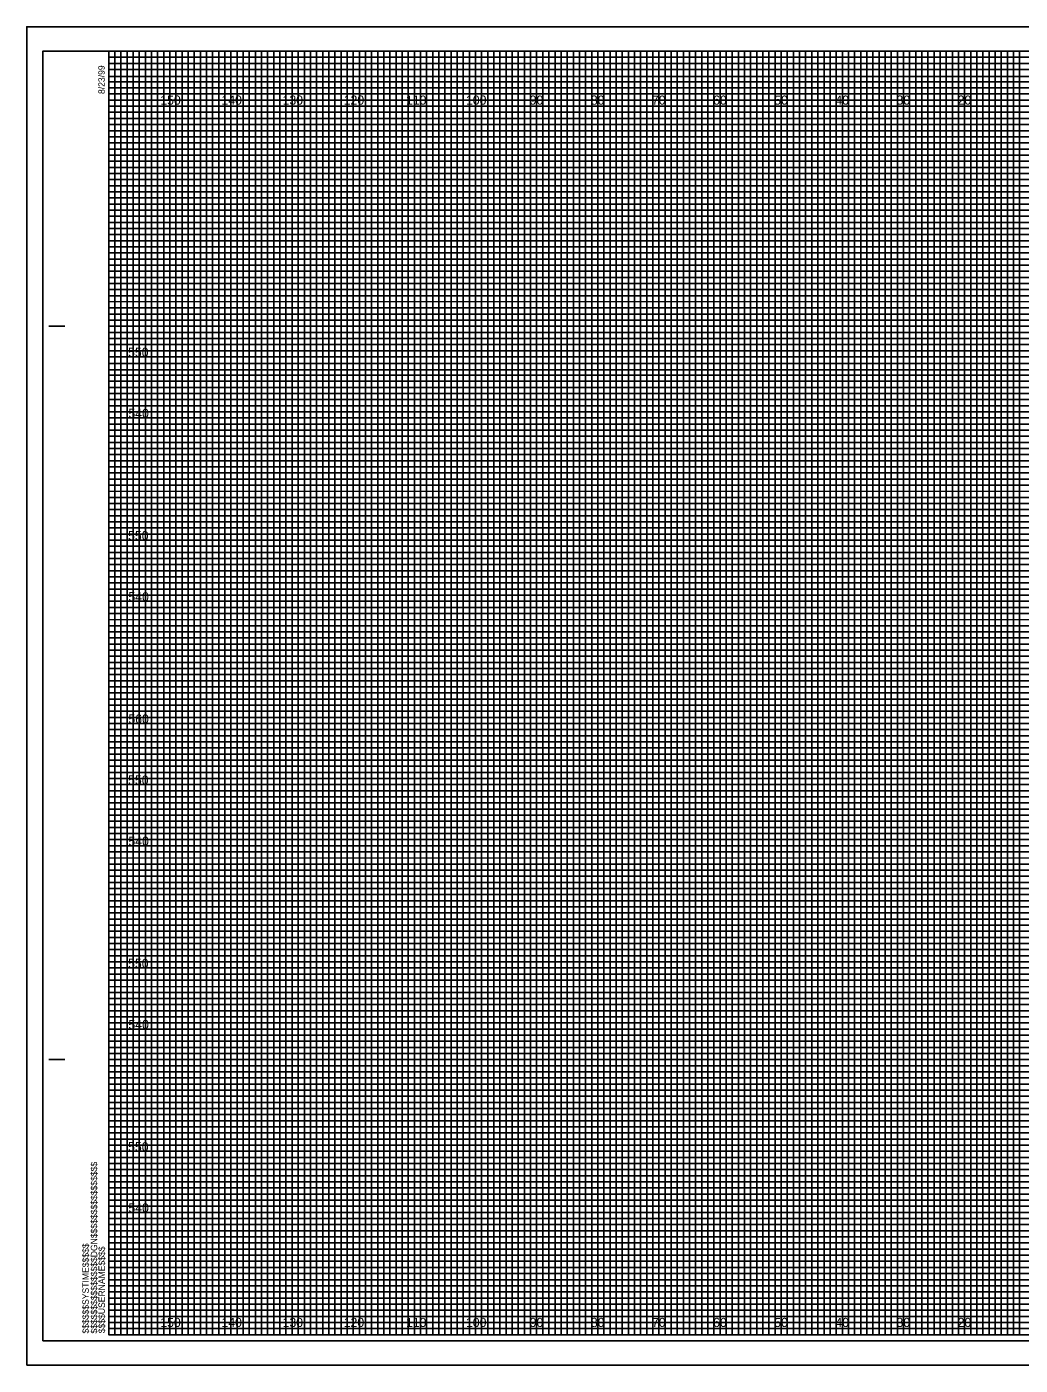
# Model space of a CAD drawing. Extents: x -13 to 323, y -5 to 214.
# Drawn here: x -13.4 to 149.1, y -5 to 214 of the extents above; entities that cross this region are included whole.
import ezdxf

# ---------------------------------------------------------------- set-up
doc = ezdxf.new("R2010")
doc.units = 0
for name, color, linetype in [('Prop XS Elevation Labels', 7, 'Continuous'), ('Prop XS Offset Labels', 7, 'Continuous'), ('Sheet Cross Section CELL', 7, 'Continuous'), ('Sheet Cross Section Grid Major CELL', 7, 'Continuous'), ('Sheet Cross Section Grid Middle CELL', 7, 'Continuous'), ('Sheet Cross Section Grid Minor 1 CELL', 7, 'Continuous'), ('Sheet Cross Section Grid Minor 2 CELL', 7, 'Continuous'), ('Sheet Cutting Line CELL', 7, 'Continuous'), ('Sheet DOT Grid CELL', 7, 'Continuous'), ('Sheet Plot Border Inside CELL', 7, 'Continuous'), ('Sheet Plot Border Outside CELL', 7, 'Continuous')]:
    doc.layers.add(name, color=color, linetype=linetype)

msp = doc.modelspace()

# ---------------------------------------------------------------- linework, layer by layer
at = {"layer": 'Sheet Cross Section CELL'}
for p, q in [((-9.8, 165), (-7.3, 165)), ((-9.7, 165), (-7.2, 165)), ((-9.8, 45), (-7.3, 45)), ((-9.7, 45), (-7.2, 45)), ((0, 0), (0, 0)), ((0, 0), (0, 0)), ((0, 0), (0, 0)), ((0, 0), (0, 0)), ((0, 0), (0, 0)), ((0, 0), (0, 0)), ((0, 0), (0, 0))]:
    msp.add_line(p, q, dxfattribs=at)
msp.add_lwpolyline([(320, 210), (0, 210), (0, 0), (320, 0)], close=True, dxfattribs=at)
at = {"layer": 'Sheet Cross Section Grid Major CELL'}
for p, q in [((10, 210), (0, 210)), ((10, 0), (10, 210)), ((30, 210), (20, 210)), ((20, 210), (20, 0)), ((30, 0), (30, 210)), ((50, 210), (40, 210)), ((40, 210), (40, 0)), ((50, 0), (50, 210)), ((70, 210), (60, 210)), ((60, 210), (60, 0)), ((70, 0), (70, 210)), ((90, 210), (80, 210)), ((80, 210), (80, 0)), ((90, 0), (90, 210)), ((110, 210), (100, 210)), ((100, 210), (100, 0)), ((110, 0), (110, 210)), ((130, 210), (120, 210)), ((120, 210), (120, 0)), ((130, 0), (130, 210)), ((150, 210), (140, 210)), ((140, 210), (140, 0)), ((20, 0), (10, 0)), ((40, 0), (30, 0)), ((60, 0), (50, 0)), ((80, 0), (70, 0)), ((100, 0), (90, 0)), ((120, 0), (110, 0)), ((140, 0), (130, 0))]:
    msp.add_line(p, q, dxfattribs=at)
for points in [[(0, 200), (320, 200), (320, 190), (0, 190)], [(0, 180), (320, 180), (320, 170), (0, 170)], [(0, 160), (320, 160), (320, 150), (0, 150)], [(0, 140), (320, 140), (320, 130), (0, 130)], [(0, 120), (320, 120), (320, 110), (0, 110)], [(0, 100), (320, 100), (320, 90), (0, 90)], [(0, 80), (320, 80), (320, 70), (0, 70)], [(0, 60), (320, 60), (320, 50), (0, 50)], [(0, 40), (320, 40), (320, 30), (0, 30)], [(0, 20), (320, 20), (320, 10), (0, 10)]]:
    msp.add_lwpolyline(points, dxfattribs=at)
at = {"layer": 'Sheet Cross Section Grid Middle CELL'}
for points in [[(0, 210), (5, 210), (5, 0), (15, 0), (15, 210), (25, 210), (25, 0), (35, 0), (35, 210), (45, 210), (45, 0), (55, 0), (55, 210), (65, 210), (65, 0), (75, 0), (75, 210), (85, 210), (85, 0), (95, 0), (95, 210), (105, 210), (105, 0), (115, 0), (115, 210), (125, 210), (125, 0), (135, 0), (135, 210), (145, 210), (145, 0), (155, 0)], [(0, 205), (275, 205)], [(0, 185), (320, 185), (320, 195), (0, 195)], [(0, 165), (320, 165), (320, 175), (0, 175)], [(0, 145), (320, 145), (320, 155), (0, 155)], [(0, 125), (320, 125), (320, 135), (0, 135)], [(0, 105), (320, 105), (320, 115), (0, 115)], [(0, 85), (320, 85), (320, 95), (0, 95)], [(0, 65), (320, 65), (320, 75), (0, 75)], [(0, 45), (320, 45), (320, 55), (0, 55)], [(0, 25), (320, 25), (320, 35), (0, 35)], [(0, 5), (320, 5), (320, 15), (0, 15)]]:
    msp.add_lwpolyline(points, dxfattribs=at)
at = {"layer": 'Sheet Cross Section Grid Minor 1 CELL'}
for p, q in [((0, 209), (260, 209)), ((260, 207.98), (0, 207.98)), ((0, 207.98), (0, 207)), ((0, 207), (260, 207)), ((260, 205.89), (0, 205.89)), ((0, 205.89), (0, 204)), ((0, 204), (320, 204))]:
    msp.add_line(p, q, dxfattribs=at)
for points in [[(0, 203), (270, 203), (320, 203), (320, 202), (0, 202)], [(0, 201), (320, 201), (320, 199), (0, 199)], [(0, 198), (320, 198), (320, 197), (0, 196.98)], [(0, 196), (320, 196), (320, 194), (0, 194)], [(0, 193), (320, 193), (320, 192), (0, 192)], [(0, 191), (320, 191), (320, 189), (0, 189)], [(0, 188), (320, 188), (320, 187), (0, 187)], [(0, 186), (320, 186), (320, 184), (0, 184)], [(0, 183), (320, 183), (320, 182), (0, 182)], [(0, 181), (320, 181), (320, 179), (0, 179)], [(0, 178), (320, 178), (320, 177), (0, 177)], [(0, 176), (320, 176), (320, 173.95), (320, 173), (320, 172), (0, 172)], [(0, 174), (320, 174), (320, 173), (0, 173)], [(0, 171), (320, 171), (320, 169), (0, 169.03)], [(0, 169.03), (320, 169), (320, 168), (0, 168)], [(0, 167), (320, 167), (320, 166), (0, 166)], [(0, 164), (320, 164), (320, 163), (0, 163)], [(0, 162), (320, 162), (320, 161), (0, 161)], [(-0.07, 158.89), (320, 158.89), (320, 157.88), (-0.07, 157.88)], [(0, 157), (320, 157), (320, 156), (0, 156)], [(0, 154), (320, 154), (320, 153), (0, 153)], [(0, 152), (320, 152), (320, 151), (0, 151)], [(0, 149), (320, 149), (320, 148), (0, 148)], [(0, 147), (320, 147), (320, 146), (0, 146)], [(0, 144), (320, 144), (320, 143), (0, 143)], [(0, 142), (320, 142), (320, 141), (0, 141)], [(0, 139), (320, 139), (319.99, 137.98), (0, 138)], [(0, 137), (320, 137), (320, 136), (0, 136)], [(0, 134), (320, 134), (320, 133), (0, 133)], [(0, 132), (320, 132), (320, 131), (0, 131)], [(0, 129), (320, 129), (320, 128), (0, 128)], [(0, 127), (320, 127), (320, 126), (0, 126)], [(0, 124), (320, 124), (320, 123), (0, 123)], [(0, 122), (320, 122), (320, 121), (0, 121)], [(0, 119), (320, 119), (320, 118), (0, 118)], [(0, 116.99), (320.07, 116.91), (320, 116), (0, 116)], [(0, 114), (320, 114), (320, 113), (0, 113)], [(0, 112), (320, 112), (320, 111), (0, 111)], [(0, 109), (320, 109), (320, 108), (0, 108)], [(0, 107), (320, 107), (320, 106), (0, 106)], [(0, 104), (320, 104), (320, 103), (0, 103)], [(0, 102), (320, 102), (320, 101), (0, 101)], [(0, 99), (320, 99), (320, 98), (0, 98)], [(0, 97), (320, 97), (320, 96), (0, 96)], [(0, 94), (320, 94), (320, 93), (0, 93)], [(0, 92), (320, 92), (320, 91), (0, 91)], [(0, 89), (320, 89), (320, 88), (0, 88)], [(0, 87), (320, 87), (320, 86), (0, 86)], [(0, 84), (320, 84), (320, 83), (0, 83)], [(0, 82), (320, 82), (320, 81), (0, 81)], [(0, 79), (320, 79), (319.99, 77.98), (0, 78)], [(0, 77), (320, 77), (320, 76), (0, 76)], [(0, 74), (320, 74), (320, 73), (0, 73)], [(0, 72), (320, 72), (320, 71), (0, 71)], [(0, 69), (320, 69), (320, 68), (0, 68)], [(0, 67), (320, 67), (320, 66), (0, 66)], [(0, 64), (320, 64), (320, 63), (0, 63)], [(0, 62), (320, 62), (320, 61), (0, 61)], [(0, 59), (320, 59), (320, 58), (0, 58)], [(0, 56.99), (320.07, 56.91), (320, 56), (0, 56)], [(0, 54), (320, 54), (320, 53), (0, 53)], [(0, 52), (320, 52), (320, 51), (0, 51)], [(0, 49), (320, 49), (320, 48), (0, 48)], [(0, 47), (320, 47), (320, 46), (0, 46)], [(0, 44), (320, 44), (320, 43), (0, 43)], [(0, 42), (320, 42), (320, 41), (0, 41)], [(0, 39), (320, 39), (320, 38), (0, 38)], [(0, 37), (320, 37), (320, 36), (0, 36)], [(0, 34), (320, 34), (320, 33), (0, 33)], [(0, 32), (320, 32), (320, 31), (0, 31)], [(0, 29), (320, 29), (320, 28), (0, 28)], [(0, 27), (320, 27), (320, 26), (0, 26)], [(0, 24), (320, 24), (320, 23), (0, 23)], [(0, 22), (320, 22), (320, 21), (0, 21)], [(0, 19), (320, 19), (320, 18), (0, 18)], [(0, 17), (320, 17), (320, 16), (0, 16)], [(0, 14), (320, 14), (320, 13), (0, 13)], [(0, 12), (320, 12), (320, 11), (0, 11)], [(0, 9), (320, 9), (320, 8), (0, 8)], [(0, 7), (320, 7), (320, 6), (0, 6)], [(0, 4), (320, 4), (320, 3), (0, 3)], [(0, 2), (320, 2), (320, 1), (0, 1)]]:
    msp.add_lwpolyline(points, dxfattribs=at)
at = {"layer": 'Sheet Cross Section Grid Minor 2 CELL'}
for points in [[(0, 0), (1, 0), (1, 210), (2, 210), (2, 0)], [(2, 0), (3, 0), (3, 210), (4, 210), (4, 0)], [(5, 0), (6, 0), (6, 210), (7, 210), (7, 0)], [(7, 0), (8, 0), (8, 210), (9, 210), (9, 0)], [(10, 0), (11, 0), (11, 210), (12, 210), (12, 0)], [(12, 0), (13, 0), (13, 210), (14, 210), (14, 0)], [(15, 0), (16, 0), (16, 210), (17, 210), (17, 0)], [(17, 0), (18, 0), (18, 210), (19, 210), (19, 0)], [(20, 0), (21, 0), (21, 210), (22, 210), (22, 0)], [(22, 0), (23, 0), (23, 210), (24, 210), (24, 0)], [(25, 0), (26, 0), (26, 210), (27, 210), (27, 0)], [(27, 0), (28, 0), (28, 210), (29, 210), (29, 0)], [(30, 0), (31, 0), (31, 210), (32, 210), (32, 0)], [(32, 0), (33, 0), (33, 210), (34, 210), (34, 0)], [(35, 0), (36, 0), (36, 210), (37, 210), (37, 0)], [(37, 0), (38, 0), (38, 210), (39, 210), (39, 0)], [(40, 0), (41, 0), (41, 210), (42, 210), (42, 0)], [(42, 0), (43, 0), (43, 210), (44, 210), (44, 0)], [(45, 0), (46, 0), (46, 210), (47, 210), (47, 0)], [(47, 0), (48, 0), (48, 210), (49, 210), (49, 0)], [(50, 0), (51, 0), (51, 210), (52, 210), (52, 0)], [(52, 0), (53, 0), (53, 210), (54, 210), (54, 0)], [(55, 0), (56, 0), (56, 210), (57, 210), (57, 0)], [(57, 0), (58, 0), (58, 210), (59, 210), (59, 0)], [(60, 0), (61, 0), (61, 210), (62, 210), (62, 0)], [(62, 0), (63, 0), (63, 210), (64, 210), (64, 0)], [(65, 0), (66, 0), (66, 210), (67, 210), (67, 0)], [(67, 0), (68, 0), (68, 210), (69, 210), (69, 0)], [(70, 0), (71, 0), (71, 210), (72, 210), (72, 0)], [(72, 0), (73, 0), (73, 210), (74, 210), (74, 0)], [(75, 0), (76, 0), (76, 210), (77, 210), (77, 0)], [(77, 0), (78, 0), (78, 210), (79, 210), (79, 0)], [(80, 0), (81, 0), (81, 210), (82, 210), (82, 0)], [(82, 0), (83, 0), (83, 210), (84, 210), (84, 0)], [(85, 0), (86, 0), (86, 210), (87, 210), (87, 0)], [(87, 0), (88, 0), (88, 210), (89, 210), (89, 0)], [(90, 0), (91, 0), (91, 210), (92, 210), (92, 0)], [(92, 0), (93, 0), (93, 210), (94, 210), (94, 0)], [(95, 0), (96, 0), (96, 210), (97, 210), (97, 0)], [(97, 0), (98, 0), (98, 210), (99, 210), (99, 0)], [(100, 0), (101, 0), (101, 210), (102, 210), (102, 0)], [(102, 0), (103, 0), (103, 210), (104, 210), (104, 0)], [(105, 0), (106, 0), (106, 210), (107, 210), (107, 0)], [(107, 0), (108, 0), (108, 210), (109, 210), (109, 0)], [(110, 0), (111, 0), (111, 210), (112, 210), (112, 0)], [(112, 0), (113, 0), (113, 210), (114, 210), (114, 0)], [(115, 0), (116, 0), (116, 210), (117, 210), (117, 0)], [(117, 0), (118, 0), (118, 210), (119, 210), (119, 0)], [(120, 0), (121, 0), (121, 210), (122, 210), (122, 0)], [(122, 0), (123, 0), (123, 210), (124, 210), (124, 0)], [(125, 0), (126, 0), (126, 210), (127, 210), (127, 0)], [(127, 0), (128, 0), (128, 210), (129, 210), (129, 0)], [(130, 0), (131, 0), (131, 210), (132, 210), (132, 0)], [(132, 0), (133, 0), (133, 210), (134, 210), (134, 0)], [(135, 0), (136, 0), (136, 210), (137, 210), (137, 0)], [(137, 0), (138, 0), (138, 210), (139, 210), (139, 0)], [(140, 0), (141, 0), (141, 210), (142, 210), (142, 0)], [(142, 0), (143, 0), (143, 210), (144, 210), (144, 0)], [(145, 0), (146, 0), (146, 210), (147, 210), (147, 0)], [(147, 0), (148, 0), (148, 210), (149, 210), (149, 0)]]:
    msp.add_lwpolyline(points, dxfattribs=at)
at = {"layer": 'Sheet Cutting Line CELL'}
for p, q in [((323.3, 214), (-13.4, 214)), ((-13.4, 214), (-13.4, -5)), ((-13.4, -5), (323.3, -5))]:
    msp.add_line(p, q, dxfattribs=at)
at = {"layer": 'Sheet DOT Grid CELL'}
for p, q in [((10, 0), (10, 210)), ((20, 0), (20, 210)), ((30, 0), (30, 210)), ((40, 0), (40, 210)), ((50, 0), (50, 210)), ((60, 0), (60, 210)), ((70, 0), (70, 210)), ((80, 0), (80, 210)), ((90, 0), (90, 210)), ((100, 0), (100, 210)), ((110, 0), (110, 210)), ((120, 0), (120, 210)), ((130, 0), (130, 210)), ((140, 0), (140, 210)), ((0, 200), (320, 200)), ((0, 190), (320, 190)), ((0, 180), (320, 180)), ((0, 170), (320, 170)), ((0, 160), (320, 160)), ((0, 150), (320, 150)), ((0, 140), (320, 140)), ((0, 130), (320, 130)), ((0, 120), (320, 120)), ((0, 110), (320, 110)), ((0, 100), (320, 100)), ((0, 90), (320, 90)), ((0, 80), (320, 80)), ((0, 70), (320, 70)), ((0, 60), (320, 60)), ((0, 50), (320, 50)), ((0, 40), (320, 40)), ((0, 30), (320, 30)), ((0, 20), (320, 20)), ((0, 10), (320, 10))]:
    msp.add_line(p, q, dxfattribs=at)
at = {"layer": 'Sheet Plot Border Inside CELL'}
msp.add_lwpolyline([(-10.8, -1), (322.4, -1), (322.4, 210), (-10.8, 210)], close=True, dxfattribs=at)
at = {"layer": 'Sheet Plot Border Outside CELL'}
msp.add_lwpolyline([(-13.4, -5), (323.3, -5), (323.3, 214), (-13.4, 214)], close=True, dxfattribs=at)

# ---------------------------------------------------------------- texts
at = {"layer": 'Prop XS Elevation Labels'}
for s, p in [('550', (3.17, 160)), ('540', (3.22, 150)), ('550', (3.17, 130)), ('540', (3.22, 120)), ('560', (3.22, 100)), ('550', (3.17, 90)), ('540', (3.22, 80)), ('550', (3.17, 60)), ('540', (3.22, 50)), ('550', (3.17, 30)), ('540', (3.22, 20))]:
    msp.add_text(s, height=1.5, dxfattribs=at).set_placement(p)
at = {"layer": 'Prop XS Offset Labels'}
for s, p in [('150', (8.44, 201.25)), ('140', (18.44, 201.25)), ('130', (28.44, 201.25)), ('120', (38.44, 201.25)), ('110', (48.62, 201.25)), ('100', (58.44, 201.25)), ('90', (68.86, 201.25)), ('80', (78.86, 201.25)), ('70', (88.86, 201.25)), ('60', (98.86, 201.25)), ('50', (108.86, 201.25)), ('40', (118.86, 201.25)), ('30', (128.86, 201.25)), ('20', (138.86, 201.25)), ('150', (8.44, 1.25)), ('140', (18.44, 1.25)), ('130', (28.44, 1.25)), ('120', (38.44, 1.25)), ('110', (48.62, 1.25)), ('100', (58.44, 1.25)), ('90', (68.86, 1.25)), ('80', (78.86, 1.25)), ('70', (88.86, 1.25)), ('60', (98.86, 1.25)), ('50', (108.86, 1.25)), ('40', (118.86, 1.25)), ('30', (128.86, 1.25)), ('20', (138.86, 1.25))]:
    msp.add_text(s, height=1.5, dxfattribs=at).set_placement(p)
at = {"layer": 'Sheet Cross Section CELL'}
for s, p in [('8/23/99', (-0.65, 203)), ('$$$$$$$$$$$$$$$$DGN$$$$$$$$$$$$$$$$', (-1.88, 0.18)), ('$$$$$$SYSTIME$$$$$', (-3.26, 0.18)), ('$$$$USERNAME$$$$', (-0.62, 0.23))]:
    msp.add_text(s, height=1.05, rotation=90, dxfattribs=at).set_placement(p)

doc.saveas('drawing.dxf')
